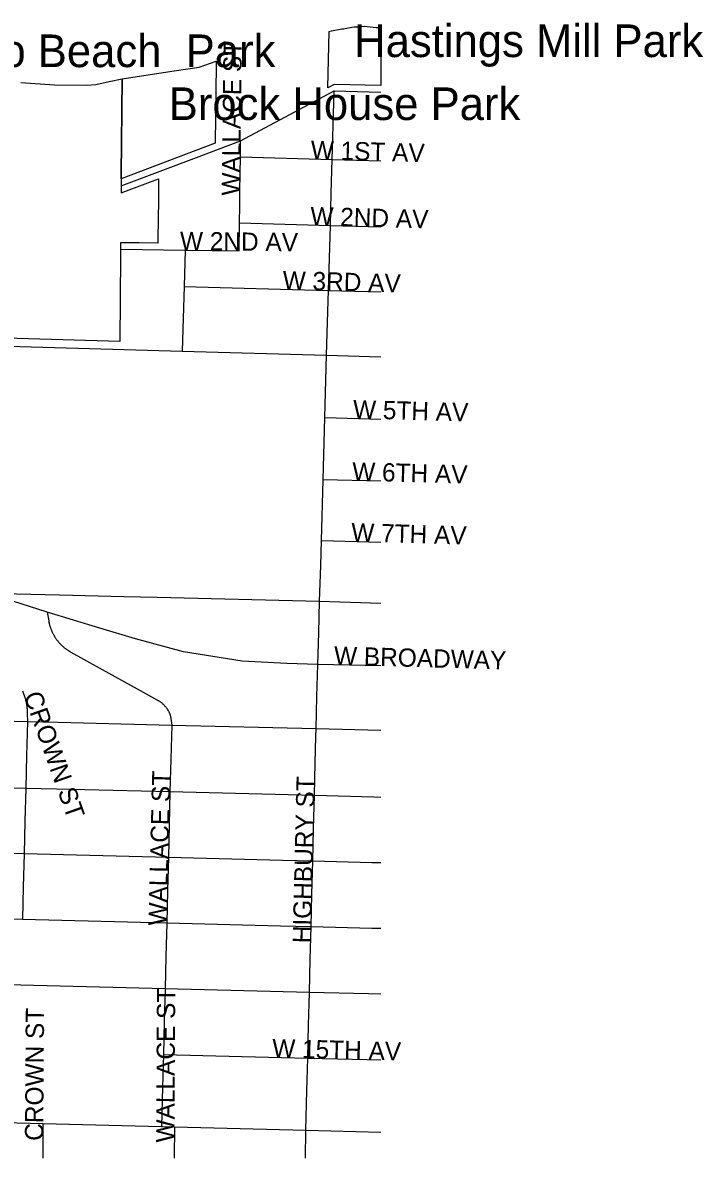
# Model space of a CAD drawing. Extents: x 482780 to 486928, y 5455974 to 5459836.
# Drawn here: x 485885 to 486928, y 5456108 to 5457848 of the extents above; entities that cross this region are included whole.
import ezdxf

# ---------------------------------------------------------------- set-up
doc = ezdxf.new("R2010")
doc.units = 0
for name, color, linetype in [('ParkLabels', 7, 'Continuous'), ('Parks', 7, 'Continuous'), ('StreetNames', 7, 'Continuous'), ('Streets', 7, 'Continuous')]:
    doc.layers.add(name, color=color, linetype=linetype)

msp = doc.modelspace()

# ---------------------------------------------------------------- linework, layer by layer
at = {"layer": 'Parks'}
for points in [[(486434, 5457751.8), (486362.9, 5457753.7), (486352.7, 5457748.3), (486355.1, 5457834.5), (486358.8, 5457835.5), (486374.4, 5457838.7), (486376.9, 5457838.6), (486389.5, 5457841.3), (486393.4, 5457841.8), (486399.5, 5457841.7), (486408.7, 5457842.6), (486426.9, 5457840.9), (486434, 5457840.9)], [(486037.7, 5457762.3), (486047.3, 5457763.8), (486117.3, 5457774.6), (486138.3, 5457777.7), (486155.7, 5457780), (486182, 5457789.1), (486181.9, 5457783.6), (486180.3, 5457663.4), (486036.2, 5457608.8), (486036.3, 5457616)]]:
    msp.add_lwpolyline(points, close=True, dxfattribs=at)
msp.add_lwpolyline([(485882.5, 5457756.7), (485933.8, 5457753), (485983.4, 5457752.3), (485997.3, 5457753.5), (486017.6, 5457757.9), (486037.7, 5457762.3), (486036.3, 5457616), (486036.2, 5457608.8), (486036, 5457587.3), (486064.8, 5457598.2), (486093.6, 5457609.1), (486093.2, 5457570.1), (486093, 5457553), (486092.5, 5457510.4), (486063.9, 5457510.7), (486035.3, 5457511), (486035.1, 5457490.9), (486033.9, 5457359.8), (485806.1, 5457366.2)], dxfattribs=at)
at = {"layer": 'Streets'}
for points in [[(486036.2, 5457598), (486151.5, 5457641.7), (486219.2, 5457667.3), (486362.7, 5457743.7), (486434, 5457741.7)], [(486318.9, 5456108), (486319.2, 5456151.1), (486320.7, 5456211.4), (486322.1, 5456261.6), (486323.3, 5456311.9), (486324.7, 5456362.2), (486325.9, 5456412.4), (486327.3, 5456462.6), (486328.5, 5456512.9), (486329.9, 5456563.3), (486331.1, 5456613.5), (486332.4, 5456663.7), (486333.6, 5456714), (486334.6, 5456754), (486334.8, 5456766.4), (486336.3, 5456815.8), (486337.7, 5456864.9), (486339.1, 5456913.4), (486340.4, 5456961.5), (486342, 5457016.4), (486343.1, 5457054.7), (486345.7, 5457147.9), (486348.4, 5457243.2), (486351.1, 5457338.5), (486352.6, 5457389.3), (486353.9, 5457437.9), (486355.4, 5457487.5), (486356.8, 5457537.1), (486358.2, 5457586.7), (486359.7, 5457638.5), (486361.2, 5457690.3), (486362.7, 5457743.7)], [(486217, 5457498.8), (486217.5, 5457541), (486217.9, 5457568.6), (486218.2, 5457590.7), (486218.9, 5457642.4), (486219.2, 5457667.3)], [(486218.9, 5457642.4), (486359.7, 5457638.5), (486434, 5457636.4)], [(486434, 5457535), (486356.8, 5457537.1), (486217.5, 5457541)], [(486035.3, 5457501), (486134.4, 5457499.8), (486217, 5457498.8)], [(486134.4, 5457499.8), (486132.7, 5457444.1), (486131.4, 5457395.5), (486129.9, 5457344.8)], [(486132.7, 5457444.1), (486353.9, 5457437.9), (486434, 5457435.6)], [(485489.1, 5457363.1), (486129.9, 5457344.8), (486351.1, 5457338.5), (486434, 5457336.2)], [(486348.4, 5457243.2), (486434, 5457240.8)], [(486434, 5457145.5), (486345.7, 5457147.9)], [(486343.1, 5457054.7), (486434, 5457052.1)], [(484570.9, 5457006.5), (484791.9, 5457000.8), (485013, 5456994.9), (485233.9, 5456989.1), (485350.6, 5456986.1), (485466.4, 5456983.2), (485769.4, 5456975.7), (485831.1, 5456974.2), (485941.5, 5456971.5), (486040.3, 5456969), (486091.5, 5456967.8), (486340.4, 5456961.5), (486434, 5456958.7)], [(486434, 5456862.4), (486337.7, 5456864.9), (486290.2, 5456866.4), (486221.7, 5456870), (486131.5, 5456884.3), (486057.9, 5456904), (486003.2, 5456920.6), (485922.7, 5456945.1), (485831.1, 5456974.2)], [(485922.7, 5456945.1), (485925.1, 5456931.5), (485925.3, 5456930.6), (485925.8, 5456927.8), (485925.6, 5456928.8), (485925.8, 5456927.9), (485926, 5456927), (485926.3, 5456926.1), (485926.5, 5456925.2), (485926.8, 5456924.1), (485927, 5456923.4), (485927.3, 5456922.6), (485927.5, 5456921.9), (485927.5, 5456921.8), (485927.9, 5456920.8), (485928.2, 5456919.9), (485928.5, 5456919.1), (485928.8, 5456918.2), (485929.2, 5456917.4), (485929.5, 5456916.5), (485929.9, 5456915.7), (485930.2, 5456914.8), (485930.6, 5456914), (485931, 5456913.2), (485931.4, 5456912.3), (485931.9, 5456911.5), (485932.3, 5456910.7), (485932.7, 5456909.9), (485933.2, 5456909.1), (485933.6, 5456908.3), (485933.9, 5456908), (485934.1, 5456907.5), (485934.6, 5456906.7), (485935.1, 5456906), (485935.6, 5456905.2), (485936.1, 5456904.5), (485936.7, 5456903.7), (485937.2, 5456902.9), (485937.7, 5456902.2), (485938.3, 5456901.5), (485938.9, 5456900.8), (485939.4, 5456900), (485940, 5456899.3), (485940.6, 5456898.6), (485941.2, 5456897.9), (485941.8, 5456897.2), (485942.4, 5456896.6), (485943.1, 5456895.9), (485943.2, 5456895.8), (485943.7, 5456895.3), (485944.4, 5456894.6), (485945.1, 5456894), (485945.7, 5456893.3), (485946.4, 5456892.7), (485947.1, 5456892.1), (485947.8, 5456891.5), (485948.5, 5456890.9), (485949.2, 5456890.3), (485949.9, 5456889.8), (485950.7, 5456889.1), (485951.3, 5456888.6), (485952.1, 5456888.1), (485952.9, 5456887.5), (485953.6, 5456887), (485954.3, 5456886.5), (485954.6, 5456886.4), (485955.2, 5456886), (485955.9, 5456885.5), (485956.6, 5456885), (485956.9, 5456884.9), (485958.3, 5456884.1), (485959.1, 5456883.6), (486065.1, 5456824.9), (486091.7, 5456810.2), (486092.6, 5456809.7), (486093.4, 5456809.3), (486094.1, 5456808.8), (486094.8, 5456808.3), (486095.5, 5456807.8), (486096.2, 5456807.3), (486096.9, 5456806.8), (486097.7, 5456806.3), (486098.3, 5456805.7), (486099, 5456805.2), (486099.7, 5456804.6), (486100, 5456804.3), (486100.3, 5456804), (486100.9, 5456803.4), (486101.5, 5456802.8), (486102.2, 5456802.2), (486102.7, 5456801.5), (486103.3, 5456800.9), (486103.9, 5456800.2), (486104.4, 5456799.6), (486105, 5456798.8), (486105.5, 5456798.2), (486106, 5456797.5), (486106.5, 5456796.7), (486107, 5456796), (486107.4, 5456795.3), (486107.9, 5456794.5), (486108.1, 5456794.2), (486108.3, 5456793.8), (486108.8, 5456793), (486109.1, 5456792.3), (486109.5, 5456791.4), (486109.9, 5456790.6), (486110.3, 5456789.9), (486110.6, 5456789.1), (486110.9, 5456788.2), (486111.2, 5456787.4), (486111.5, 5456786.6), (486111.8, 5456785.7), (486113.6, 5456771.9)], [(484342.2, 5456817.9), (484565.7, 5456812), (484786.9, 5456806.1), (485007.9, 5456800.2), (485229, 5456794.3), (485450.2, 5456788.6), (485671.5, 5456783.1), (485892.6, 5456777.5), (485939.7, 5456776.3), (486113.6, 5456771.9), (486334.8, 5456766.4), (486434, 5456763.9)], [(485884.8, 5456824.2), (485885.4, 5456822.8), (485885.9, 5456821.4), (485886.5, 5456820), (485887, 5456818.6), (485887.5, 5456817.2), (485888, 5456815.8), (485888.4, 5456814.4), (485888.9, 5456812.9), (485889.3, 5456811.5), (485889.7, 5456810), (485890, 5456808.6), (485890.3, 5456807.1), (485890.6, 5456805.6), (485890.9, 5456804.2), (485891.1, 5456802.7), (485891.4, 5456801.2), (485891.6, 5456799.7), (485891.7, 5456798.2), (485891.9, 5456796.8), (485892, 5456795.3), (485892.1, 5456793.8), (485892.2, 5456792.3), (485892.2, 5456790.8), (485892.2, 5456789.7), (485892.6, 5456777.5), (485891.2, 5456725.1), (485889.9, 5456674.9), (485888.7, 5456624.6), (485887.4, 5456574.3), (485886.1, 5456524), (485884.8, 5456473.7)], [(486113.6, 5456771.9), (486112.3, 5456719.6), (486111, 5456669.3), (486109.8, 5456619), (486108.6, 5456568.7), (486107.3, 5456518.4), (486106, 5456468.2), (486104.7, 5456417.9), (486103.4, 5456367.6), (486102.1, 5456317.4), (486100.8, 5456267.2), (486099.5, 5456217), (486097.9, 5456156.7)], [(486434, 5456661.1), (486423.2, 5456661.4), (486332.4, 5456663.7), (486111, 5456669.3), (485937.1, 5456673.7), (485889.9, 5456674.9), (485668.8, 5456680.4), (485447.5, 5456686), (485226.4, 5456691.7), (485005.3, 5456697.6), (484784.2, 5456703.3), (484563, 5456709.4), (484339.5, 5456715.3)], [(486434, 5456560.5), (486420.6, 5456560.9), (486329.9, 5456563.3), (486283.2, 5456564.3), (486108.6, 5456568.7), (485887.4, 5456574.3), (485666.1, 5456579.8), (485445.1, 5456585.6), (485223.8, 5456591.3), (485002.6, 5456597.1), (484781.5, 5456602.9), (484560.4, 5456608.9), (484336.8, 5456614.8)], [(486434, 5456459.9), (486420.6, 5456460.2), (486327.3, 5456462.6), (486280.6, 5456463.8), (486106, 5456468.2), (485884.8, 5456473.7), (485663.6, 5456479.2), (485442.5, 5456485), (485221.3, 5456490.8), (485047.9, 5456495.3), (485000, 5456496.5), (484778.9, 5456502.5), (484557.8, 5456508.3), (484334.2, 5456514.3)], [(486434, 5456359.3), (486415.2, 5456359.8), (486324.7, 5456362.2), (486103.4, 5456367.6), (485882.3, 5456373.2), (485834.9, 5456374.4), (485661, 5456378.8), (485440, 5456384.6), (485218.7, 5456390.3), (485035.8, 5456395.1), (484997.5, 5456396.1), (484776.3, 5456402), (484555.1, 5456407.8), (484331.5, 5456413.8)], [(486100.8, 5456267.2), (486322.1, 5456261.6), (486412.7, 5456259.3), (486434, 5456258.7)], [(484325.9, 5456202.5), (484549.4, 5456196.6), (484704.2, 5456193.1), (484770.8, 5456190.9), (484992, 5456185.1), (485214.3, 5456179.3), (485434.4, 5456173.5), (485655.6, 5456167.9), (485697.4, 5456166.9), (485829.6, 5456163.6), (485876.9, 5456162.5), (485916.8, 5456161.4), (486097.9, 5456156.7), (486117.8, 5456156.2), (486319.2, 5456151.1), (486434, 5456148.1)], [(485916.5, 5456108), (485916.8, 5456161.4)], [(486117.8, 5456156.2), (486117.5, 5456108)]]:
    msp.add_lwpolyline(points, dxfattribs=at)

# ---------------------------------------------------------------- texts
at = {"layer": 'ParkLabels'}
for s, p in [('Hastings Mill Park', (486393.3, 5457795.5)), ('Jericho Beach  Park', (485674.2, 5457780.1)), ('Brock House Park', (486109.1, 5457699))]:
    msp.add_text(s, height=50, dxfattribs=at).set_placement(p)
at = {"layer": 'StreetNames'}
for s, rotation, p in [('WALLACE ST', 89.248, (486218.1, 5457583)), ('W 1ST AV', 358.3959, (486326.4, 5457639.4)), ('W 2ND AV', 358.3991, (486325.8, 5457538)), ('W 2ND AV', 359.3159, (486126.1, 5457499.9)), ('W 3RD AV', 358.3878, (486283.4, 5457439.8)), ('W 5TH AV', 358.4199, (486391.2, 5457242)), ('W 6TH AV', 358.4117, (486389.9, 5457146.7)), ('W 7TH AV', 358.3521, (486388.5, 5457053.4)), ('W BROADWAY', 358.3967, (486362.1, 5456864.4)), ('CROWN ST', 289.5336, (485886.4, 5456817.6)), ('WALLACE ST', 88.5407, (486105.8, 5456464.3)), ('HIGHBURY ST', 88.6118, (486326.9, 5456437.2)), ('WALLACE ST', 89.6619, (486117.7, 5456132.1)), ('CROWN ST', 89.5925, (485916.6, 5456134.7)), ('W 15TH AV', 358.552, (486267.4, 5456262.9))]:
    msp.add_text(s, height=28, rotation=rotation, dxfattribs=at).set_placement(p)

doc.saveas('drawing.dxf')
